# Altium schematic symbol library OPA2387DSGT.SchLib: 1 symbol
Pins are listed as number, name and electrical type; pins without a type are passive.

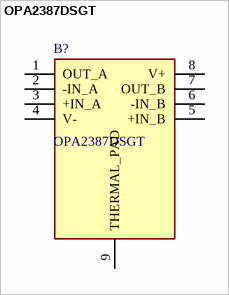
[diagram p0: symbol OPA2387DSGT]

## OPA2387DSGT
designator B?
Precision Amplifiers Ultra-high precision, zero-drift, low-input-bias-current op amp; Manufacturer_Name: Texas Instruments; Geometry.Height: 0.8mm
footprint SON50P200X200X80-9N
pins: 1 OUT_A, 2 -IN_A, 3 +IN_A, 4 V-, 5 +IN_B, 6 -IN_B, 7 OUT_B, 8 V+, 9 THERMAL_PAD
